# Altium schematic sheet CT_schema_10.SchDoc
size 281 x 153 mm
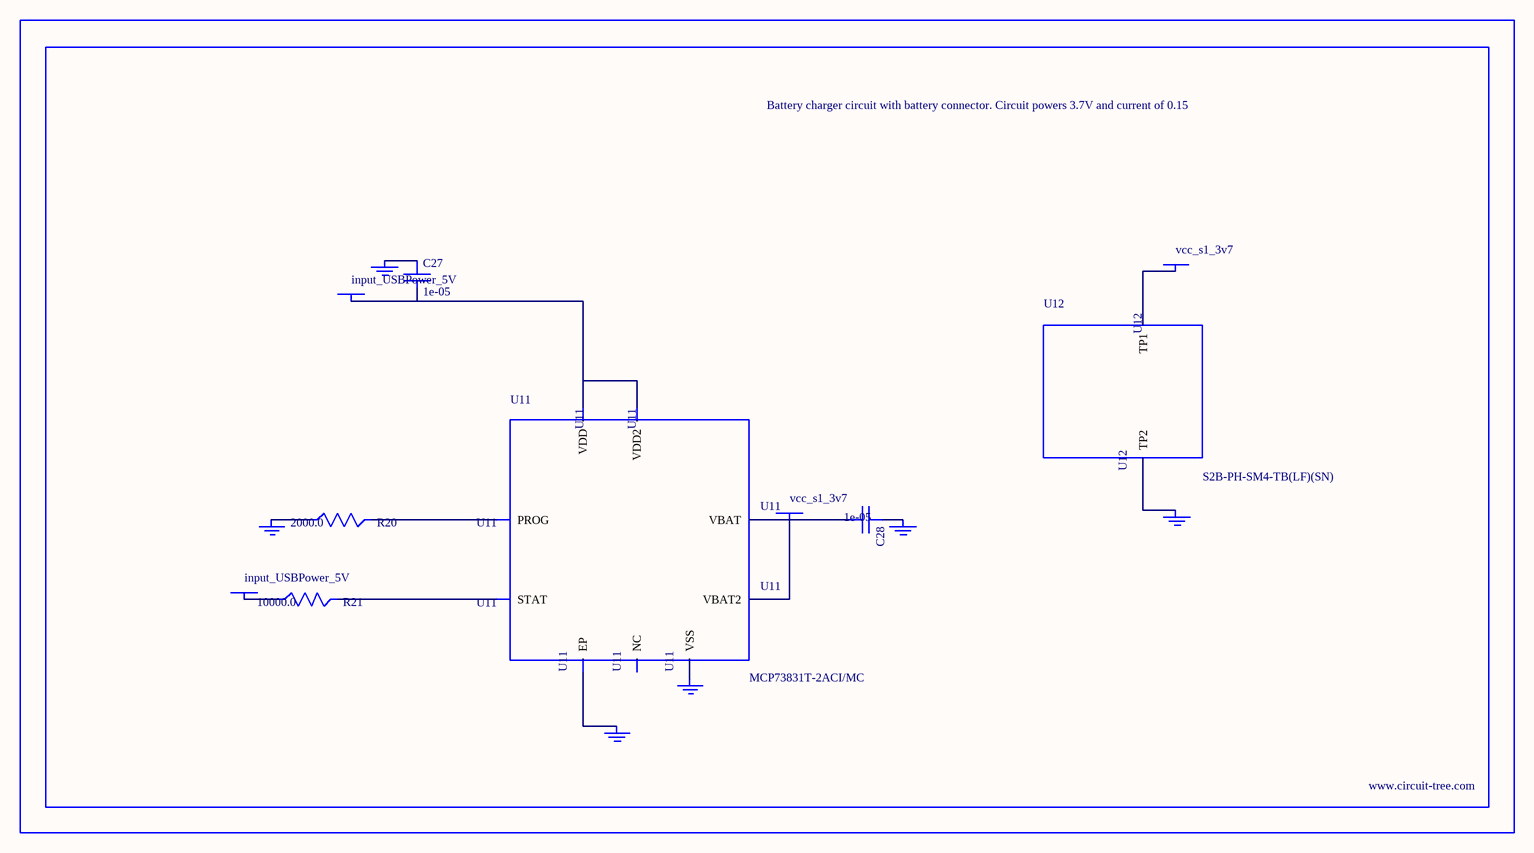
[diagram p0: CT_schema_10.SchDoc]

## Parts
BORDER9  (no value)
C27  1e-05  [C1206]
C28  1e-05  [C1206]
GND_INSTANCE_9_0  (no value)
GND_INSTANCE_9_1  (no value)
GND_INSTANCE_9_2  (no value)
GND_INSTANCE_9_3  (no value)
GND_INSTANCE_9_4  (no value)
GND_INSTANCE_9_5  (no value)
POWER_INSTANCE_9_0  input_USBPower_5V
POWER_INSTANCE_9_1  input_USBPower_5V
POWER_INSTANCE_9_2  vcc_s1_3v7
POWER_INSTANCE_9_3  vcc_s1_3v7
R20  2000.0  [R0603]
R21  10000.0  [R0603]
U11  MCP73831T-2ACI/MC  [DFN8_2X3MC]
U12  S2B-PH-SM4-TB(LF)(SN)  [JST-2-SMD]

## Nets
NetC27_1: C27.1 GND_INSTANCE_9_0.0(GND)
NetC27_2: C27.2 POWER_INSTANCE_9_0.0(PWR) U11.1(VDD) U11.2(VDD2)
NetC28_1: C28.1 GND_INSTANCE_9_1.0(GND)
NetC28_2: C28.2 POWER_INSTANCE_9_2.0(PWR) U11.3(VBAT) U11.4(VBAT2)
NetGND_INSTANCE_9_2_0: GND_INSTANCE_9_2.0(GND) R20.1
NetGND_INSTANCE_9_3_0: GND_INSTANCE_9_3.0(GND) U11.9(EP)
NetGND_INSTANCE_9_4_0: GND_INSTANCE_9_4.0(GND) U11.6(VSS)
NetGND_INSTANCE_9_5_0: GND_INSTANCE_9_5.0(GND) U12.2(TP2)
NetPOWER_INSTANCE_9_1_0: POWER_INSTANCE_9_1.0(PWR) R21.1
NetPOWER_INSTANCE_9_3_0: POWER_INSTANCE_9_3.0(PWR) U12.1(TP1)
NetR20_2: R20.2 U11.8(PROG)
NetR21_2: R21.2 U11.5(STAT)

Not connected (* = marked no-connect by the designer): U11 7(NC)

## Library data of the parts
BORDER9 = BORDER_PAGE9
C27 C28 = C1206C106K3RACTU
GND_INSTANCE_9_0-GND_INSTANCE_9_5 = GND
POWER_INSTANCE_9_0-POWER_INSTANCE_9_3 = PWR
R20 = RC0603JR-072KL
R21 = RC0603JR-0710KL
